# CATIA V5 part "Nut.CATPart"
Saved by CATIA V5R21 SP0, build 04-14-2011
Part number: nut
Bounding box of the stored display mesh (mm): x -13.856 to 13.856, y 0 to 9, z -12 to 12
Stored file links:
  D:\CATIA V5R21 E-RESOURCES\CATIA-V5R21\catia-v5r21-Prts\c14_catia_v5r21_prt\c14-catia-v5r21-figr-14-26 & 27\Part & Asm\Nut.CATPart
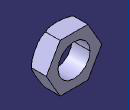
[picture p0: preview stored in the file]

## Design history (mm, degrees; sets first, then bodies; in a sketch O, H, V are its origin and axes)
Body1 (main body)
  Sketch1 on zx-plane, origin (0, 0, 0), H (-1, 0, 0), V (0, 0, 1)
    circle A1 centre (0, 0) radius 8
    construction circle A2 centre (0, 0) radius 12
    point P1 (-6.9282, -12)
    point P2 (6.9282, -12)
    point P3 (13.8564, 0)
    point P4 (6.9282, 12)
    point P5 (-6.9282, 12)
    point P6 (-13.8564, 0)
    point P7 (0, -12)
    line L1 (-6.9282, -12) -> (6.9282, -12)
    line L2 (6.9282, -12) -> (13.8564, 0)
    line L3 (13.8564, 0) -> (6.9282, 12)
    line L4 (6.9282, 12) -> (-6.9282, 12)
    line L5 (-6.9282, 12) -> (-13.8564, 0)
    line L6 (-13.8564, 0) -> (-6.9282, -12)
    construction line L7 (0, 0) -> (0, -12)
    construction circle A3 centre (0, 0) radius 13.8564
    construction arc A4 centre (-6.9282, 12) radius 13.8564 from (6.9282, 12) to (-13.8564, 0) cw
    construction arc A5 centre (6.9282, -12) radius 13.8564 from (13.8564, 0) to (-6.9282, -12) ccw
    radius A1 = 8
    radius A2 = 12
    coincidence: P7 A2, A3 P1, A3 P2, A3 P3, A3 P4, A3 P5, A3 P6, A4 O, A5 O
    vertical: L7 V
    midpoint: P7 L1
    parallelism: L1 L4
  Pad1: profile Sketch1, direction (0, 1, 0), length 9
  Sketch2 on xy-plane, origin (0, 0, 0), H (1, 0, 0), V (0, 1, 0)
    projected line E1 (10.7061, 0) -> (13.8564, 0) from edge of Pad1
    point P1 (13.8564, 0)
    projected line E2 (13.8564, 0) -> (13.8564, 1.8188) from edge of Pad1
    point P2 (13.8564, 0)
    arc A1 centre (10.7061, 3.6376) radius 3.6376 from (10.7061, 0) to (13.8564, 1.8188) ccw
    coincidence: P1 P2
    tangency: A1 E1
  Groove1: profile Sketch2, axis axis of face of Pad1, angle 360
